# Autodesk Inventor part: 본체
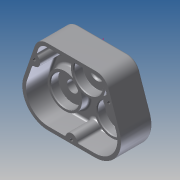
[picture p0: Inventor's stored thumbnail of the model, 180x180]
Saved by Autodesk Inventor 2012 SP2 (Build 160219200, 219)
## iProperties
Created: 2014-12
Part Number: 본체
Material: Default
Document SubType Name: 모델링
Designer: cad-02
Density: 1 g/cm^3
Sheet Metal Width: 0.000 mm
Sheet Metal Length: 0.000 mm
Sheet Metal Area: 0.000 mm^2
Author: cad-02
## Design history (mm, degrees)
sketch "스케치1"
  geometry: L1 (-47, 0)-(47, 0); L2 (-47, 0)-(-66.564, -56.804); L3 (-32.527, -104.527)-(32.527, -104.527); L4 (66.565, -56.804)-(47, 0); A1 r 36 centre (-32.527, -68.527) between (-66.564, -56.804) and (-32.527, -104.527); A2 r 36 centre (32.527, -68.527) between (32.527, -104.527) and (66.565, -56.804); 2 further points
  constraints: 8 end point, 4 point on circle, 4 tangent, 2 centre point, 1 coincident, 1 equal length, 1 horizontal, 1 midpoint, 1 parallel
  dimensions: "d0" = 94 distance of L1.start L1.end; "d142" = 104.527 distance between parallel lines of L1 L3; "d178" = 72 diameter of A1; "d179" = 72 diameter of A2; "d181" = 133.129 distance of L4.start L2.end
extrude "돌출1" new body sketch "스케치1" distance "d2" = 44; taper "d3" = 0 deg
fillet "모깎기7" dims "d167" = 18
feature "쉘4" dims "d260" = 10, "d261" = 5
sketch "스케치21"
  geometry: C1 r 20 at (32.527, 68.527); C2 r 20 at (-32.527, 68.527); A1 r 36 centre (32.527, 68.527) between (66.564, 56.804) and (32.527, 104.527) reference; A2 r 36 centre (-32.527, 68.527) between (-32.527, 104.527) and (-66.565, 56.804) reference; 1 further point
  constraints: 2 centre point, 2 coincident
  dimensions: "d220" = 40 diameter of C1; "d221" = 40 diameter of C2
extrude "돌출7" join sketch "스케치21" distance "d222" = 7; taper "d223" = -5 deg
hole "구멍14" diameter "d226" = 15.5; stored, may be unused: countersink angle "d230" = 90 deg, drill point angle "d232" = 0 deg; dims "d224" = 10, "d225" = 10, "d227" = 6, "d228" = 30, "d229" = 7, "d231" = 17
hole "구멍15" diameter "d235" = 15.5; stored, may be unused: countersink angle "d239" = 90 deg, drill point angle "d241" = 0 deg; dims "d233" = 10, "d234" = 10, "d236" = 6, "d237" = 30, "d238" = 7, "d240" = 17
sketch "스케치26"
  geometry: L1 (0, 5)-(68.324, 5) reference; L2 (66.689, -99.527)-(1.635, -99.527) reference; C1 r 7.75 at (1.635, -63.527) reference; C2 r 7.75 at (66.689, -63.527) reference; A1 r 24 centre (1.635, -63.527) between (13.051, -42.416) and (22.746, -52.111); A2 r 24 centre (66.689, -63.527) between (45.578, -52.111) and (55.273, -42.416); A3 r 46 centre (34.162, -31) between (1.635, -63.527) and (66.689, -63.527); A4 r 24 centre (34.162, -31) between (22.746, -52.111) and (45.578, -52.111); A5 r 24 centre (34.162, -31) between (55.273, -42.416) and (13.051, -42.416); 2 further points
  constraints: 10 point on circle, 5 centre point, 1 coincident, 1 midpoint, 1 vertical alignment
  dimensions: "d262" = 48 diameter of A1; "d263" = 48 diameter of A2; "d265" = 36 distance from line of L1 A4.centre; "d266" = 92 diameter of A3; "d267" = 36 distance from line of A1.centre L2; "d268" = 36 distance from line of A2.centre L2; "d269" = 24 radius of A5; "d270" = 24 radius of A4
extrude "돌출10" join sketch "스케치26" distance "d271" = 11; taper "d272" = 0 deg
hole "구멍17" diameter "d275" = 40; stored, may be unused: countersink angle "d279" = 90 deg, drill point angle "d281" = 0 deg; dims "d273" = 10, "d274" = 10, "d276" = 6, "d277" = 30, "d278" = 7, "d280" = 12
hole "구멍18" diameter "d284" = 20; stored, may be unused: countersink angle "d288" = 90 deg, drill point angle "d290" = 0 deg; dims "d282" = 10, "d283" = 10, "d285" = 6, "d286" = 30, "d287" = 7, "d289" = 3
hole "구멍19" diameter "d293" = 40; stored, may be unused: countersink angle "d297" = 90 deg, drill point angle "d299" = 0 deg; dims "d291" = 10, "d292" = 10, "d294" = 6, "d295" = 30, "d296" = 7, "d298" = 11
hole "구멍20" diameter "d302" = 40; stored, may be unused: countersink angle "d306" = 90 deg, drill point angle "d308" = 0 deg; dims "d300" = 10, "d301" = 10, "d303" = 6, "d304" = 30, "d305" = 7, "d307" = 11
sketch "스케치27"
  geometry: L1 (46.453, -13.767)-(61.837, -58.432) reference; L2 (32.527, -99.527)-(-32.527, -99.527) reference; L3 (-61.837, -58.432)-(-46.453, -13.767) reference; L4 (-34.162, 0)-(34.162, 0) reference; A1 r 8 centre (0, -99.527) between (8, -99.527) and (-8, -99.527); A2 r 8 centre (-51.7, -29) between (-54.305, -36.564) and (-49.095, -21.436); A3 r 8 centre (51.7, -29) between (49.095, -21.436) and (54.305, -36.564); 1 further point
  constraints: 8 point on line, 6 point on circle, 3 centre point, 1 midpoint
  dimensions: "d309" = 16 diameter of A1; "d310" = 16 diameter of A2; "d311" = 16 diameter of A3; "d312" = 29 distance from line of A3.centre L4; "d313" = 29 distance from line of A2.centre L4
extrude "돌출11" join sketch "스케치27" stored distance "d314" = 11; taper "d315" = 0 deg
sketch "스케치28"
  geometry: 1 further point
sketch "스케치29"
  geometry: 1 further point
hole "구멍21" diameter "d318" = 4.134; stored, may be unused: countersink angle "d322" = 90 deg, drill point angle "d324" = 118 deg; dims "d316" = 10, "d317" = 10, "d319" = 20, "d320" = 30, "d321" = 7, "d323" = 23
hole "구멍22" diameter "d327" = 4.134; stored, may be unused: countersink angle "d331" = 90 deg, drill point angle "d333" = 118 deg; dims "d325" = 10, "d326" = 10, "d328" = 20, "d329" = 30, "d330" = 7, "d332" = 23
hole "구멍23" diameter "d336" = 4.134; stored, may be unused: countersink angle "d340" = 90 deg, drill point angle "d342" = 118 deg; dims "d334" = 10, "d335" = 10, "d337" = 20, "d338" = 30, "d339" = 7, "d341" = 23
fillet "모깎기9" dims "d343" = 3
fillet "모깎기10" dims "d344" = 0.1
fillet "모깎기11" dims "d345" = 0.3
fillet "모깎기12" dims "d346" = 3
fillet "모깎기13" dims "d347" = 3
chamfer "모따기1" distance "d348" = 1; stored, may be unused: second distance "d349" = 2, angle "d350" = 45 deg
fillet "모깎기14" dims "d351" = 3
fillet "모깎기15" dims "d352" = 3
node "솔리드1"
other parameters: "d13" = 48, "d159" = 48, "K계수" = 4.4, "d184" = 48, "d264" = 48
